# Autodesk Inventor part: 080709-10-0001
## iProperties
Created: 2008-07
Part Number: 080709-10-0001
Material: Standard
Document SubType Name: Modellieren
Designer: WH
Density: 1 g/cm^3
Stock Number: 080709-10-0001
Author: WH
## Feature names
1. Wandstärke1
2. Grobblech1
3. Biegung1
